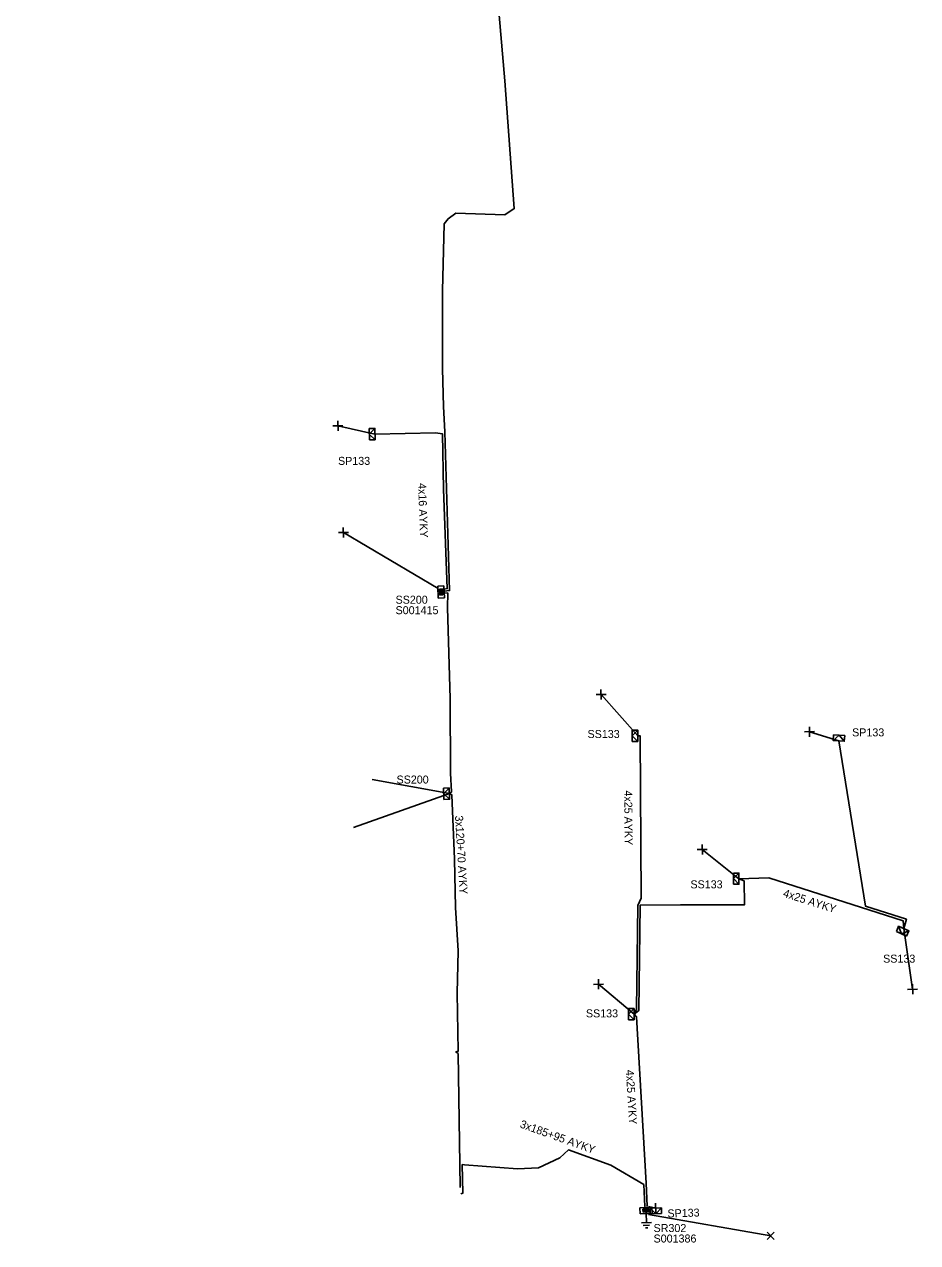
# Model space of a CAD drawing. Extents: x -762500 to -761285, y -1155006 to -1154135.
# Drawn here: x -762500 to -762389.1, y -1154595 to -1154443.6 of the extents above; entities that cross this region are included whole.
import ezdxf

# ---------------------------------------------------------------- set-up
doc = ezdxf.new("R2010")
doc.units = 0
for name, color, linetype in [('Vrstva 15', 7, 'Continuous'), ('Vrstva 28', 7, 'Continuous'), ('Vrstva 29', 7, 'Continuous'), ('Vrstva 30', 7, 'Continuous'), ('Vrstva 31', 7, 'Continuous'), ('Vrstva 33', 7, 'Continuous'), ('Vrstva 34', 7, 'Continuous'), ('Vrstva 5', 7, 'Continuous'), ('Vrstva 52', 7, 'Continuous'), ('Vrstva 59', 7, 'Continuous'), ('Vrstva 6', 7, 'Continuous')]:
    doc.layers.add(name, color=color, linetype=linetype)

msp = doc.modelspace()

# ---------------------------------------------------------------- linework, layer by layer
at = {"layer": 'Vrstva 15'}
for points in [[(-762422.115, -1154592.487), (-762423.364, -1154592.53)], [(-762422.783, -1154591.259), (-762422.739, -1154592.509)], [(-762422.345, -1154592.805), (-762423.132, -1154592.833)], [(-762422.718, -1154593.133), (-762422.846, -1154593.138)], [(-762422.585, -1154593.129), (-762422.718, -1154593.133)]]:
    msp.add_lwpolyline(points, dxfattribs=at)
at = {"layer": 'Vrstva 28'}
for points in [[(-762447.893, -1154513.382), (-762448.642, -1154513.408)], [(-762448.642, -1154513.408), (-762448.59, -1154514.907)], [(-762448.063, -1154513.76), (-762448.44, -1154513.774)], [(-762448.44, -1154513.774), (-762448.414, -1154514.517)], [(-762448.037, -1154514.504), (-762448.063, -1154513.76)], [(-762447.84, -1154514.881), (-762447.893, -1154513.382)], [(-762448.59, -1154514.907), (-762447.84, -1154514.881)], [(-762448.414, -1154514.517), (-762448.037, -1154514.504)], [(-762448.108, -1154513.809), (-762448.391, -1154513.819)], [(-762448.391, -1154513.819), (-762448.369, -1154514.468)], [(-762448.369, -1154514.468), (-762448.085, -1154514.458)], [(-762448.154, -1154513.858), (-762448.343, -1154513.865)], [(-762448.343, -1154513.865), (-762448.323, -1154514.42)], [(-762448.323, -1154514.42), (-762448.134, -1154514.413)], [(-762448.199, -1154513.907), (-762448.294, -1154513.91)], [(-762448.294, -1154513.91), (-762448.278, -1154514.371)], [(-762448.278, -1154514.371), (-762448.183, -1154514.367)], [(-762448.245, -1154513.95), (-762448.232, -1154514.328)], [(-762448.183, -1154514.367), (-762448.199, -1154513.907)], [(-762448.134, -1154514.413), (-762448.154, -1154513.858)], [(-762448.085, -1154514.458), (-762448.108, -1154513.809)], [(-762422.059, -1154590.591), (-762423.558, -1154590.643)], [(-762423.558, -1154590.643), (-762423.532, -1154591.392)], [(-762422.436, -1154590.787), (-762423.18, -1154590.813)], [(-762423.18, -1154590.813), (-762423.166, -1154591.191)], [(-762422.481, -1154590.836), (-762423.131, -1154590.858)], [(-762423.131, -1154590.858), (-762423.121, -1154591.142)], [(-762422.527, -1154590.885), (-762423.082, -1154590.904)], [(-762423.082, -1154590.904), (-762423.075, -1154591.093)], [(-762422.573, -1154590.934), (-762423.033, -1154590.95)], [(-762423.033, -1154590.95), (-762423.03, -1154591.044)], [(-762422.99, -1154590.995), (-762422.612, -1154590.982)], [(-762422.569, -1154591.028), (-762422.573, -1154590.934)], [(-762422.52, -1154591.074), (-762422.527, -1154590.885)], [(-762422.472, -1154591.119), (-762422.481, -1154590.836)], [(-762422.423, -1154591.165), (-762422.436, -1154590.787)], [(-762422.033, -1154591.34), (-762422.059, -1154590.591)], [(-762423.532, -1154591.392), (-762422.033, -1154591.34)], [(-762423.166, -1154591.191), (-762422.423, -1154591.165)], [(-762423.121, -1154591.142), (-762422.472, -1154591.119)], [(-762423.075, -1154591.093), (-762422.52, -1154591.074)], [(-762423.03, -1154591.044), (-762422.569, -1154591.028)]]:
    msp.add_lwpolyline(points, dxfattribs=at)
at = {"layer": 'Vrstva 31'}
for points in [[(-762457.172, -1154493.84), (-762456.472, -1154493.828), (-762456.448, -1154495.227), (-762457.148, -1154495.24)], [(-762457.172, -1154493.84), (-762457.148, -1154495.24)], [(-762457.16, -1154494.54), (-762456.472, -1154493.828)], [(-762457.16, -1154494.54), (-762456.448, -1154495.227)], [(-762424.52, -1154531.308), (-762424.52, -1154532.708)], [(-762424.52, -1154532.008), (-762423.82, -1154531.308)], [(-762424.52, -1154531.308), (-762423.82, -1154531.308), (-762423.82, -1154532.708), (-762424.52, -1154532.708)], [(-762398.12, -1154531.991), (-762398.169, -1154532.689), (-762399.566, -1154532.591), (-762399.517, -1154531.893)], [(-762398.819, -1154531.942), (-762399.566, -1154532.591)], [(-762398.12, -1154531.991), (-762399.517, -1154531.893)], [(-762398.819, -1154531.942), (-762398.169, -1154532.689)], [(-762424.52, -1154532.008), (-762423.82, -1154532.708)], [(-762447.945, -1154538.512), (-762447.245, -1154538.488), (-762447.196, -1154539.887), (-762447.896, -1154539.911)], [(-762447.945, -1154538.512), (-762447.896, -1154539.911)], [(-762447.92, -1154539.212), (-762447.245, -1154538.488)], [(-762447.92, -1154539.212), (-762447.196, -1154539.887)], [(-762411.951, -1154549.057), (-762411.951, -1154550.457)], [(-762411.951, -1154549.757), (-762411.251, -1154549.057)], [(-762411.951, -1154549.057), (-762411.251, -1154549.057), (-762411.251, -1154550.457), (-762411.951, -1154550.457)], [(-762411.951, -1154549.757), (-762411.251, -1154550.457)], [(-762391.707, -1154556.314), (-762391.422, -1154555.675), (-762390.143, -1154556.244), (-762390.428, -1154556.884)], [(-762391.067, -1154556.599), (-762391.422, -1154555.675)], [(-762391.707, -1154556.314), (-762390.428, -1154556.884)], [(-762391.067, -1154556.599), (-762390.143, -1154556.244)], [(-762424.971, -1154565.887), (-762424.971, -1154567.287)], [(-762424.971, -1154566.587), (-762424.271, -1154565.887)], [(-762424.971, -1154565.887), (-762424.271, -1154565.887), (-762424.271, -1154567.287), (-762424.971, -1154567.287)], [(-762424.971, -1154566.587), (-762424.271, -1154567.287)], [(-762422.268, -1154591.404), (-762422.293, -1154590.705), (-762420.893, -1154590.656), (-762420.869, -1154591.355)], [(-762421.569, -1154591.38), (-762422.293, -1154590.705)], [(-762421.569, -1154591.38), (-762420.893, -1154590.656)], [(-762422.268, -1154591.404), (-762420.869, -1154591.355)]]:
    msp.add_lwpolyline(points, dxfattribs=at)
at = {"layer": 'Vrstva 34'}
for points in [[(-762461.685, -1154493.511), (-762460.435, -1154493.489)], [(-762461.049, -1154494.125), (-762461.071, -1154492.875)], [(-762460.369, -1154507.375), (-762460.391, -1154506.125)], [(-762461.005, -1154506.761), (-762459.755, -1154506.739)], [(-762429.005, -1154526.891), (-762427.755, -1154526.869)], [(-762428.369, -1154527.505), (-762428.391, -1154526.255)], [(-762403.125, -1154531.511), (-762401.875, -1154531.489)], [(-762402.489, -1154532.125), (-762402.511, -1154530.875)], [(-762415.799, -1154546.755), (-762415.821, -1154545.505)], [(-762416.435, -1154546.141), (-762415.185, -1154546.119)], [(-762429.315, -1154562.891), (-762428.065, -1154562.869)], [(-762428.679, -1154563.505), (-762428.701, -1154562.255)], [(-762390.315, -1154563.511), (-762389.065, -1154563.489)], [(-762389.679, -1154564.125), (-762389.701, -1154562.875)], [(-762422.215, -1154590.691), (-762420.965, -1154590.669)], [(-762421.579, -1154591.305), (-762421.601, -1154590.055)], [(-762407.752, -1154593.688), (-762406.868, -1154594.572)], [(-762407.752, -1154594.572), (-762406.868, -1154593.688)]]:
    msp.add_lwpolyline(points, dxfattribs=at)
at = {"layer": 'Vrstva 5'}
for points in [[(-762447.87, -1154514.06), (-762447.19, -1154513.97), (-762447.78, -1154494.23), (-762447.96, -1154491.1), (-762448.07, -1154486.41), (-762448.09, -1154476.73), (-762447.86, -1154468.4), (-762447.37, -1154467.77), (-762446.41, -1154467.09), (-762440.35, -1154467.28), (-762439.17, -1154466.5), (-762440.35, -1154450.63), (-762443.14, -1154417.97), (-762440.42, -1154401.72), (-762438.88, -1154383.02), (-762437.94, -1154382.67), (-762438.76, -1154382.21), (-762437.05, -1154361.64), (-762436.79, -1154359.77), (-762436.82, -1154358.87), (-762440.94, -1154348.18), (-762469.48, -1154287.46), (-762481.67, -1154268.61), (-762500, -1154250.46)], [(-762447.88, -1154513.79), (-762447.49, -1154513.72), (-762447.93, -1154501.38), (-762448.08, -1154494.49), (-762448.95, -1154494.37), (-762456.46, -1154494.53)], [(-762447.22, -1154539.19), (-762446.95, -1154538.97), (-762447.06, -1154536.64), (-762447.11, -1154527.43), (-762447.44, -1154516.08), (-762447.42, -1154514.26), (-762447.87, -1154514.27)], [(-762424.27, -1154566.59), (-762423.98, -1154565.98), (-762423.81, -1154553.07), (-762423.38, -1154552.16), (-762423.51, -1154532.02), (-762423.82, -1154532.01)], [(-762424.27, -1154566.59), (-762423.69, -1154566.15), (-762423.52, -1154553.06), (-762418.53, -1154553.02), (-762410.58, -1154553.01), (-762410.61, -1154550.03), (-762411.25, -1154549.76), (-762407.54, -1154549.67), (-762390.86, -1154555), (-762390.78, -1154555.96), (-762390.46, -1154554.8), (-762395.53, -1154553.19), (-762398.87, -1154532.64)], [(-762445.87, -1154588.11), (-762445.91, -1154585.26), (-762446.14, -1154571.49), (-762446.4, -1154571.29), (-762446.14, -1154571.19), (-762446.24, -1154563.99), (-762446.12, -1154558.72), (-762446.44, -1154553.34), (-762446.57, -1154547.32), (-762446.92, -1154539.34), (-762447.22, -1154539.19)], [(-762422.75, -1154590.49), (-762422.65, -1154590.43), (-762422.76, -1154587.58), (-762423.99, -1154566.92), (-762424.27, -1154566.59)], [(-762445.81, -1154588.92), (-762445.56, -1154588.83), (-762445.61, -1154585.28), (-762445.34, -1154585.31), (-762438.77, -1154585.8), (-762436.16, -1154585.69), (-762433.51, -1154584.44), (-762432.44, -1154583.45), (-762427.17, -1154585.34), (-762423.05, -1154587.76), (-762422.95, -1154590.48), (-762422.88, -1154590.49)]]:
    msp.add_lwpolyline(points, dxfattribs=at)
at = {"layer": 'Vrstva 52'}
msp.add_lwpolyline([(-762422.48, -1154590.49), (-762421.59, -1154590.68)], dxfattribs=at)
at = {"layer": 'Vrstva 59'}
for points in [[(-762456.46, -1154494.53), (-762461.06, -1154493.5)], [(-762448.6, -1154513.7), (-762460.38, -1154506.75)], [(-762423.82, -1154532.01), (-762428.38, -1154526.88)], [(-762398.87, -1154532.64), (-762402.5, -1154531.5)], [(-762447.22, -1154539.19), (-762456.81, -1154537.42)], [(-762447.22, -1154539.19), (-762459.13, -1154543.38)], [(-762411.25, -1154549.76), (-762415.81, -1154546.13)], [(-762390.78, -1154555.96), (-762389.69, -1154563.5)], [(-762424.27, -1154566.59), (-762428.69, -1154562.88)], [(-762422.47, -1154591.47), (-762407.31, -1154594.13)]]:
    msp.add_lwpolyline(points, dxfattribs=at)

# ---------------------------------------------------------------- texts
at = {"layer": 'Vrstva 29'}
for s, p in [('S001415', (-762453.9, -1154516.9)), ('S001386', (-762421.86, -1154594.96))]:
    msp.add_text(s, height=0.9943, dxfattribs=at).set_placement(p)
at = {"layer": 'Vrstva 30'}
for s, p in [('SS200', (-762453.9, -1154515.6)), ('SR302', (-762421.86, -1154593.66))]:
    msp.add_text(s, height=0.9943, dxfattribs=at).set_placement(p)
at = {"layer": 'Vrstva 33'}
for s, p in [('SP133', (-762461.05, -1154498.35)), ('SS133', (-762430.06, -1154532.28)), ('SP133', (-762397.2, -1154532.08)), ('SS200', (-762453.78, -1154537.94)), ('SS133', (-762417.28, -1154550.96)), ('SS133', (-762393.35, -1154560.19)), ('SS133', (-762430.26, -1154566.99))]:
    msp.add_text(s, height=0.9943, dxfattribs=at).set_placement(p)
msp.add_text('SP133', height=0.9943, rotation=1.79044, dxfattribs=at).set_placement((-762420.12, -1154591.85))
at = {"layer": 'Vrstva 6'}
for s, height, rotation, p in [('4x16 AYKY', 0.9943, 272.0517, (-762451.11, -1154500.62)), ('4x25 AYKY', 0.9943, 270.3555, (-762425.5, -1154538.8)), ('3x120+70 AYKY', 0.99428, 273.40392, (-762446.52, -1154541.94)), ('4x25 AYKY', 0.9943, 342.26966, (-762405.85, -1154551.97)), ('4x25 AYKY', 0.9943, 273.40937, (-762425.3, -1154573.53)), ('3x185+95 AYKY', 0.99428, 340.27045, (-762438.54, -1154580.64))]:
    msp.add_text(s, height=height, rotation=rotation, dxfattribs=at).set_placement(p)

doc.saveas('drawing.dxf')
